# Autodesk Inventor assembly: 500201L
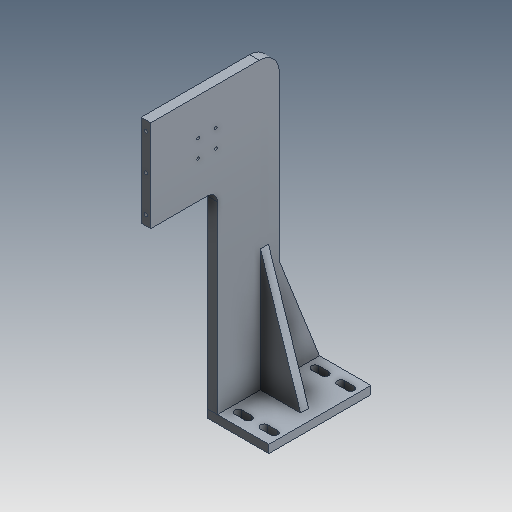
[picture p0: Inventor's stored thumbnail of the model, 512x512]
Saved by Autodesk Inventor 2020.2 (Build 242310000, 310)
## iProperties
Created: 1999-11
Part Number: 500201L
Document SubType Name: Assembly
Designer: sspink
Mass: 1640.92 g
Surface Area: 1292.4 cm^2
Volume: 605.504 cm^3
Density: 2.71 g/cm^3
Control State: 0
Checked Out: False
Last Check In By: sspink
Last Check In Date: 1999-12-22
Master: False
Shininess: 0.0
Length Units: 11269
Angle Units: 11279
Time Units: 11290
Mass Units: 11283
Length Display Precision: 3
Angle Display Precision: 2
Compacted: True
Dimensions: 366x210x76 mm
Mass: 1,641 kg
Density: 0.0
Volumn: 0.0
Area: 0.0
PropertySet Name: Model Information
Author: sspink
Revision Number: -
Title: 500201L
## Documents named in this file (4)
- D:\07 - DEMODATEN\OTX 2019 - Dataset - UPDATE - Dez2019\Designs\07-Packing machine\500201L.iam
- D:\07 - DEMODATEN\OTX 2019 - Dataset - UPDATE - Dez2019\Designs\07-Packing machine\Parts\ADSK-011296.ipt
- D:\07 - DEMODATEN\OTX 2019 - Dataset - UPDATE - Dez2019\Designs\07-Packing machine\Parts\ADSK-011297.ipt
- D:\07 - DEMODATEN\OTX 2019 - Dataset - UPDATE - Dez2019\Designs\07-Packing machine\Parts\ADSK-011298.ipt
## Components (3 placed, 3 different names)
1. ADSK-011296:1 — Passend:6, Flush:2, Flush:4, Mate:4, Flush:5, Passend:3, Passend:7, Fluchtend:6
2. ADSK-011297:1 — Passend:6, Passend:3, Passend:5
3. ADSK-011298:1 — Flush:2, Passend:5, Passend:7, Fluchtend:6
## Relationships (9: Mate 5, Flush 4)
- Passend:6 [Mate]: ADSK-011296:1 ↔ ADSK-011297:1
- Flush:2: ADSK-011296:1 ↔ ADSK-011298:1
- Flush:4: ADSK-011296:1
- Mate:4: ADSK-011296:1
- Flush:5: ADSK-011296:1
- Passend:3 [Mate]: ADSK-011296:1 ↔ ADSK-011297:1
- Passend:5 [Mate]: ADSK-011297:1 ↔ ADSK-011298:1
- Passend:7 [Mate]: ADSK-011296:1 ↔ ADSK-011298:1
- Fluchtend:6 [Flush]: ADSK-011296:1 ↔ ADSK-011298:1
